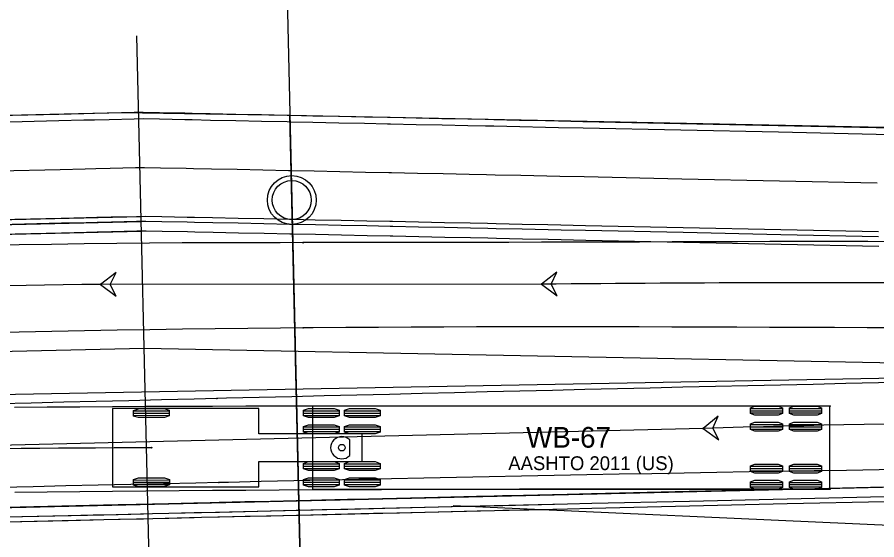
# Model space of a CAD drawing. Extents: x -70 to 701944, y -4 to 666871.
# Drawn here: x 664765.9 to 664853.9, y 656687.8 to 656741.4 of the extents above; entities that cross this region are included whole.
import ezdxf

# ---------------------------------------------------------------- set-up
doc = ezdxf.new("R2010")
doc.units = 0
for name, color, linetype in [('R_Detour', 7, 'Continuous'), ('R_Draft', 7, 'Continuous'), ('R_Drive', 7, 'Continuous'), ('R_No Plot', 7, 'Continuous'), ('R_Proposed Road', 7, 'Continuous'), ('R_Striping', 7, 'Continuous'), ('R_Water', 7, 'Continuous'), ('T_Indications', 7, 'Continuous'), ('T_Vehicle Path Lt Minor', 7, 'Continuous'), ('T_Vehicle Path Rt', 7, 'Continuous')]:
    doc.layers.add(name, color=color, linetype=linetype)

msp = doc.modelspace()

# ---------------------------------------------------------------- linework, layer by layer
at = {"layer": 'R_Detour'}
msp.add_line((664792.031, 656807.534), (664794.944, 656682.847), dxfattribs=at)
at = {"layer": 'R_Draft'}
msp.add_line((664779.481, 656682.485), (664778.149, 656739.517), dxfattribs=at)
at = {"layer": 'R_Drive'}
msp.add_lwpolyline([(664863.88, 656729.191), (664853.873, 656729.402), (664843.865, 656729.613), (664833.857, 656729.824), (664823.85, 656730.035), (664821.348, 656730.087), (664820.018, 656730.115), (664817.367, 656730.171), (664814.716, 656730.227), (664813.842, 656730.245), (664812.063, 656730.283), (664809.412, 656730.339), (664806.761, 656730.395), (664804.112, 656730.45), (664803.834, 656730.456), (664801.465, 656730.506), (664798.821, 656730.562), (664796.181, 656730.617), (664793.827, 656730.667), (664793.546, 656730.673), (664790.916, 656730.728), (664788.292, 656730.784), (664785.675, 656730.839), (664783.819, 656730.878), (664783.066, 656730.894), (664780.464, 656730.948), (664778.815, 656730.983), (664777.873, 656730.961), (664775.292, 656730.901), (664773.817, 656730.866), (664772.722, 656730.841), (664770.163, 656730.781), (664763.819, 656730.633)], dxfattribs=at)
at = {"layer": 'R_No Plot'}
msp.add_line((667813.841, 656555.62), (664810.544, 656691.315), dxfattribs=at)
for points in [[(664793.811, 656731.333), (664776.567, 656731.598), (664678.361, 656729.304), (664666.519, 656729.359), (664635.945, 656732.6), (664627.222, 656684.211), (664649.677, 656681.165), (664794.944, 656682.847)], [(664946.11, 656728.25), (664793.811, 656731.333), (664794.944, 656682.847), (664896.068, 656685.209), (664944.911, 656685.1)]]:
    msp.add_lwpolyline(points, close=True, dxfattribs=at)
msp.add_circle((664794.013, 656722.669), 2.5, dxfattribs=at)
at = {"layer": 'R_Proposed Road'}
msp.add_line((664679.299, 656689.148), (664895.858, 656694.206), dxfattribs=at)
for points in [[(664863.865, 656729.858), (664853.857, 656730.069), (664843.849, 656730.279), (664833.842, 656730.49), (664823.834, 656730.701), (664821.332, 656730.754), (664820.002, 656730.782), (664817.352, 656730.838), (664814.7, 656730.893), (664813.826, 656730.912), (664812.048, 656730.949), (664809.396, 656731.005), (664806.745, 656731.061), (664804.096, 656731.117), (664803.819, 656731.123), (664801.449, 656731.173), (664798.805, 656731.228), (664796.166, 656731.284), (664793.811, 656731.333), (664793.53, 656731.339), (664790.901, 656731.395), (664788.277, 656731.45), (664785.66, 656731.505), (664783.803, 656731.544), (664783.05, 656731.56), (664780.449, 656731.615), (664778.8, 656731.65), (664777.857, 656731.628), (664775.277, 656731.567), (664773.801, 656731.533), (664772.707, 656731.507), (664770.148, 656731.448), (664763.804, 656731.299)], [(664863.88, 656729.191), (664853.873, 656729.402), (664843.865, 656729.613), (664833.857, 656729.824), (664823.85, 656730.035), (664821.348, 656730.087), (664820.018, 656730.115), (664817.367, 656730.171), (664814.716, 656730.227), (664813.842, 656730.245), (664812.063, 656730.283), (664809.412, 656730.339), (664806.761, 656730.395), (664804.112, 656730.45), (664803.834, 656730.456), (664801.465, 656730.506), (664798.821, 656730.562), (664796.181, 656730.617), (664793.827, 656730.667), (664793.546, 656730.673), (664790.916, 656730.728), (664788.292, 656730.784), (664785.675, 656730.839), (664783.819, 656730.878), (664783.066, 656730.894), (664780.464, 656730.948), (664778.815, 656730.983), (664777.873, 656730.961), (664775.292, 656730.901), (664773.817, 656730.866), (664772.722, 656730.841), (664770.163, 656730.781), (664763.819, 656730.633)], [(664853.989, 656724.403), (664843.982, 656724.614), (664833.974, 656724.825), (664823.966, 656725.036), (664821.464, 656725.089), (664820.134, 656725.117), (664817.484, 656725.172), (664814.832, 656725.228), (664813.959, 656725.247), (664812.18, 656725.284), (664809.528, 656725.34), (664806.877, 656725.396), (664804.228, 656725.452), (664803.951, 656725.458), (664801.581, 656725.507), (664798.938, 656725.563), (664796.298, 656725.619), (664793.943, 656725.668), (664793.663, 656725.674), (664791.033, 656725.73), (664788.409, 656725.785), (664785.792, 656725.84), (664783.936, 656725.879), (664783.182, 656725.895), (664780.581, 656725.95), (664778.932, 656725.985), (664777.989, 656725.963), (664775.409, 656725.902), (664773.933, 656725.868), (664772.839, 656725.842), (664770.28, 656725.782), (664763.936, 656725.634)], [(664854.106, 656719.405), (664844.098, 656719.616), (664834.091, 656719.826), (664824.083, 656720.037), (664821.581, 656720.09), (664820.251, 656720.118), (664817.601, 656720.174), (664814.949, 656720.23), (664814.076, 656720.248), (664812.297, 656720.286), (664809.645, 656720.341), (664806.994, 656720.397), (664804.345, 656720.453), (664804.068, 656720.459), (664801.698, 656720.509), (664799.055, 656720.564), (664796.415, 656720.62), (664794.06, 656720.67), (664793.78, 656720.676), (664791.15, 656720.731), (664788.526, 656720.786), (664785.909, 656720.841), (664784.053, 656720.881), (664783.299, 656720.896), (664780.698, 656720.951), (664779.049, 656720.986), (664778.106, 656720.964), (664775.526, 656720.904), (664774.05, 656720.869), (664772.956, 656720.844), (664770.397, 656720.784), (664764.053, 656720.636)], [(664854.118, 656718.905), (664844.11, 656719.116), (664834.102, 656719.327), (664824.095, 656719.537), (664821.593, 656719.59), (664820.263, 656719.618), (664817.612, 656719.674), (664814.961, 656719.73), (664814.087, 656719.748), (664812.309, 656719.786), (664809.657, 656719.842), (664807.006, 656719.897), (664804.357, 656719.953), (664804.08, 656719.959), (664801.71, 656720.009), (664799.066, 656720.065), (664796.426, 656720.12), (664794.072, 656720.17), (664793.791, 656720.176), (664791.161, 656720.231), (664788.537, 656720.286), (664785.92, 656720.342), (664784.064, 656720.381), (664783.311, 656720.397), (664780.709, 656720.451), (664779.06, 656720.486), (664778.118, 656720.464), (664775.538, 656720.404), (664774.062, 656720.369), (664772.968, 656720.344), (664770.409, 656720.284), (664764.064, 656720.136)], [(664854.141, 656717.905), (664844.133, 656718.116), (664834.126, 656718.327), (664824.118, 656718.538), (664821.616, 656718.59), (664820.286, 656718.618), (664817.636, 656718.674), (664814.984, 656718.73), (664814.111, 656718.748), (664812.332, 656718.786), (664809.68, 656718.842), (664807.029, 656718.898), (664804.38, 656718.953), (664804.103, 656718.959), (664801.733, 656719.009), (664799.09, 656719.065), (664796.45, 656719.121), (664794.095, 656719.17), (664793.815, 656719.176), (664791.185, 656719.231), (664788.561, 656719.287), (664785.944, 656719.342), (664784.088, 656719.381), (664783.334, 656719.397), (664780.733, 656719.452), (664779.084, 656719.486), (664778.141, 656719.464), (664775.561, 656719.404), (664774.085, 656719.37), (664772.991, 656719.344), (664770.432, 656719.284), (664764.088, 656719.136)], [(664924.976, 656694.446), (664922.27, 656694.461), (664915.666, 656694.465), (664914.882, 656694.463), (664909.063, 656694.424), (664904.788, 656694.373), (664902.46, 656694.338), (664895.858, 656694.206), (664894.706, 656694.179), (664884.709, 656693.946), (664874.712, 656693.712), (664864.714, 656693.479), (664854.717, 656693.245), (664844.72, 656693.012), (664834.723, 656692.778), (664824.725, 656692.545), (664822.226, 656692.486), (664814.728, 656692.311), (664804.731, 656692.078), (664794.733, 656691.844), (664784.736, 656691.611), (664779.738, 656691.494), (664774.739, 656691.377), (664764.742, 656691.144)], [(664854.717, 656693.245), (664844.72, 656693.012), (664834.723, 656692.778), (664824.725, 656692.545), (664822.226, 656692.486), (664820.897, 656692.455), (664818.25, 656692.394), (664815.601, 656692.332), (664814.728, 656692.311), (664812.951, 656692.27), (664810.302, 656692.208), (664807.654, 656692.146), (664805.008, 656692.084), (664804.731, 656692.078), (664802.364, 656692.022), (664799.723, 656691.961), (664797.086, 656691.899), (664794.733, 656691.844), (664794.453, 656691.838), (664791.826, 656691.776), (664789.205, 656691.715), (664786.59, 656691.654), (664784.736, 656691.611), (664783.984, 656691.593), (664781.385, 656691.532), (664779.738, 656691.494), (664778.795, 656691.472), (664776.215, 656691.412), (664774.739, 656691.377), (664773.645, 656691.352), (664771.086, 656691.292), (664764.742, 656691.144)], [(664924.969, 656693.446), (664922.266, 656693.461), (664915.669, 656693.465), (664914.885, 656693.463), (664909.073, 656693.424), (664904.802, 656693.374), (664902.477, 656693.338), (664895.881, 656693.206), (664894.73, 656693.18), (664884.732, 656692.946), (664874.735, 656692.713), (664864.738, 656692.479), (664854.74, 656692.246), (664844.743, 656692.012), (664834.746, 656691.779), (664824.749, 656691.545), (664822.249, 656691.487), (664814.751, 656691.312), (664804.754, 656691.078), (664794.757, 656690.844), (664784.76, 656690.611), (664779.761, 656690.494), (664774.762, 656690.377), (664764.765, 656690.144)], [(664924.965, 656692.946), (664922.264, 656692.961), (664915.67, 656692.965), (664914.887, 656692.963), (664909.078, 656692.924), (664904.809, 656692.874), (664902.485, 656692.838), (664895.893, 656692.707), (664894.741, 656692.68), (664884.744, 656692.446), (664874.747, 656692.213), (664864.749, 656691.979), (664854.752, 656691.746), (664844.755, 656691.512), (664834.758, 656691.279), (664824.76, 656691.045), (664822.261, 656690.987), (664814.763, 656690.812), (664804.766, 656690.578), (664794.769, 656690.345), (664784.771, 656690.111), (664779.773, 656689.994), (664774.774, 656689.878), (664764.777, 656689.644)], [(664854.74, 656692.246), (664844.743, 656692.012), (664834.746, 656691.779), (664824.749, 656691.545), (664822.249, 656691.487), (664820.921, 656691.456), (664818.273, 656691.394), (664815.624, 656691.332), (664814.751, 656691.312), (664812.975, 656691.27), (664810.326, 656691.208), (664807.677, 656691.146), (664805.031, 656691.084), (664804.754, 656691.078), (664802.387, 656691.023), (664799.746, 656690.961), (664797.109, 656690.899), (664794.757, 656690.844), (664794.477, 656690.838), (664791.849, 656690.777), (664789.228, 656690.715), (664786.614, 656690.654), (664784.76, 656690.611), (664784.007, 656690.593), (664781.408, 656690.533), (664779.761, 656690.494), (664778.818, 656690.472), (664776.238, 656690.412), (664774.762, 656690.377), (664773.668, 656690.352), (664771.109, 656690.292), (664764.765, 656690.144)], [(664854.752, 656691.746), (664844.755, 656691.512), (664834.758, 656691.279), (664824.76, 656691.045), (664822.261, 656690.987), (664820.932, 656690.956), (664818.285, 656690.894), (664815.636, 656690.832), (664814.763, 656690.812), (664812.986, 656690.77), (664810.337, 656690.708), (664807.689, 656690.646), (664805.043, 656690.585), (664804.766, 656690.578), (664802.399, 656690.523), (664799.758, 656690.461), (664797.121, 656690.4), (664794.769, 656690.345), (664794.488, 656690.338), (664791.861, 656690.277), (664789.24, 656690.215), (664786.625, 656690.154), (664784.771, 656690.111), (664784.019, 656690.094), (664781.42, 656690.033), (664779.773, 656689.994), (664778.83, 656689.972), (664776.25, 656689.912), (664774.774, 656689.878), (664773.68, 656689.852), (664771.121, 656689.792), (664764.777, 656689.644)]]:
    msp.add_lwpolyline(points, dxfattribs=at)
at = {"layer": 'R_Striping'}
for p, q in [((664678.925, 656705.144), (664778.898, 656707.479)), ((664778.898, 656707.479), (664895.601, 656705.203)), ((664679.018, 656701.145), (664895.601, 656705.203))]:
    msp.add_line(p, q, dxfattribs=at)
at = {"layer": 'R_Water'}
msp.add_circle((664794.013, 656722.669), 2, dxfattribs=at)
at = {"layer": 'T_Indications'}
for p, q in [((664678.61, 656718.64), (664778.582, 656720.975)), ((664678.621, 656718.14), (664778.594, 656720.475)), ((664678.645, 656717.14), (664778.617, 656719.475))]:
    msp.add_line(p, q, dxfattribs=at)
at = {"layer": 'T_Vehicle Path Lt Minor'}
for p, q in [((664790.639, 656701.284), (664775.639, 656701.284)), ((664775.639, 656701.284), (664775.639, 656693.284)), ((664777.802, 656701.045), (664781.468, 656701.064)), ((664790.639, 656698.717), (664790.639, 656701.284)), ((664795.205, 656701.055), (664798.872, 656701.055)), ((664849.139, 656701.534), (664796.139, 656701.534)), ((664796.139, 656701.534), (664796.139, 656693.034)), ((664799.405, 656701.055), (664803.072, 656701.055)), ((664840.989, 656701.305), (664844.289, 656701.305)), ((664840.989, 656701.076), (664844.289, 656701.076)), ((664844.989, 656701.305), (664848.289, 656701.305)), ((664844.989, 656701.076), (664848.289, 656701.076)), ((664849.139, 656693.034), (664849.139, 656701.534)), ((664777.803, 656700.816), (664781.47, 656700.835)), ((664777.804, 656700.587), (664781.471, 656700.606)), ((664795.205, 656700.826), (664798.872, 656700.826)), ((664795.205, 656700.597), (664798.872, 656700.597)), ((664799.405, 656700.826), (664803.072, 656700.826)), ((664799.405, 656700.597), (664803.072, 656700.597)), ((664840.989, 656700.847), (664844.289, 656700.847)), ((664844.989, 656700.847), (664848.289, 656700.847)), ((664795.205, 656699.405), (664798.872, 656699.405)), ((664795.205, 656699.176), (664798.872, 656699.176)), ((664799.405, 656699.405), (664803.072, 656699.405)), ((664799.405, 656699.176), (664803.072, 656699.176)), ((664840.989, 656699.655), (664844.289, 656699.655)), ((664840.989, 656699.426), (664844.289, 656699.426)), ((664840.989, 656699.197), (664844.289, 656699.197)), ((664844.989, 656699.655), (664848.289, 656699.655)), ((664844.989, 656699.426), (664848.289, 656699.426)), ((664844.989, 656699.197), (664848.289, 656699.197)), ((664801.239, 656698.717), (664790.639, 656698.717)), ((664795.205, 656698.947), (664798.872, 656698.947)), ((664799.405, 656698.947), (664803.072, 656698.947)), ((664801.239, 656695.851), (664801.239, 656698.717)), ((664799.947, 656696.476), (664799.947, 656698.092)), ((664790.639, 656693.284), (664790.639, 656695.851)), ((664790.639, 656695.851), (664801.239, 656695.851)), ((664795.205, 656695.622), (664798.872, 656695.622)), ((664799.405, 656695.622), (664803.072, 656695.622)), ((664795.205, 656695.392), (664798.872, 656695.392)), ((664795.205, 656695.163), (664798.872, 656695.163)), ((664799.405, 656695.392), (664803.072, 656695.392)), ((664799.405, 656695.163), (664803.072, 656695.163)), ((664840.989, 656695.372), (664844.289, 656695.372)), ((664840.989, 656695.142), (664844.289, 656695.142)), ((664840.989, 656694.913), (664844.289, 656694.913)), ((664844.989, 656695.372), (664848.289, 656695.372)), ((664844.989, 656695.142), (664848.289, 656695.142)), ((664844.989, 656694.913), (664848.289, 656694.913)), ((664777.807, 656693.962), (664781.473, 656693.981)), ((664795.205, 656693.972), (664798.872, 656693.972)), ((664799.405, 656693.972), (664803.072, 656693.972)), ((664775.639, 656693.284), (664790.639, 656693.284)), ((664775.639, 656693.284), (664775.639, 656693.284)), ((664777.808, 656693.733), (664781.474, 656693.752)), ((664777.809, 656693.504), (664781.476, 656693.523)), ((664795.205, 656693.742), (664798.872, 656693.742)), ((664795.205, 656693.513), (664798.872, 656693.513)), ((664796.139, 656693.034), (664849.139, 656693.034)), ((664796.139, 656693.034), (664796.139, 656693.034)), ((664799.405, 656693.742), (664803.072, 656693.742)), ((664799.405, 656693.513), (664803.072, 656693.513)), ((664840.989, 656693.722), (664844.289, 656693.722)), ((664840.989, 656693.492), (664844.289, 656693.492)), ((664840.989, 656693.263), (664844.289, 656693.263)), ((664844.989, 656693.722), (664848.289, 656693.722)), ((664844.989, 656693.492), (664848.289, 656693.492)), ((664844.989, 656693.263), (664848.289, 656693.263))]:
    msp.add_line(p, q, dxfattribs=at)
for points in [[(664849.139, 656701.534), (664845.605, 656701.534), (664842.072, 656701.534), (664838.539, 656701.534), (664835.005, 656701.534), (664831.472, 656701.534), (664827.939, 656701.534), (664824.405, 656701.534), (664820.872, 656701.534), (664817.339, 656701.534), (664813.805, 656701.534), (664810.272, 656701.534), (664806.739, 656701.534), (664803.205, 656701.534), (664799.672, 656701.534), (664796.139, 656701.534), (664796.139, 656701.534), (664792.722, 656701.532), (664789.305, 656701.527), (664785.889, 656701.519), (664782.472, 656701.507), (664779.055, 656701.491), (664775.639, 656701.473), (664775.639, 656701.473), (664772.295, 656701.452), (664768.952, 656701.428), (664765.609, 656701.401)], [(664849.139, 656693.034), (664845.605, 656693.034), (664842.072, 656693.034), (664838.539, 656693.034), (664835.005, 656693.033), (664831.472, 656693.032), (664827.939, 656693.03), (664824.405, 656693.026), (664820.872, 656693.022), (664817.339, 656693.016), (664813.805, 656693.009), (664810.272, 656693), (664806.739, 656692.989), (664803.205, 656692.977), (664799.672, 656692.962), (664796.139, 656692.946), (664792.722, 656692.927), (664789.306, 656692.907), (664785.889, 656692.884), (664782.473, 656692.86), (664779.056, 656692.832), (664775.64, 656692.803), (664775.64, 656692.803), (664772.304, 656692.772), (664768.968, 656692.738), (664765.633, 656692.702)]]:
    msp.add_lwpolyline(points, dxfattribs=at)
for points in [[(664777.805, 656700.53), (664777.802, 656701.102), (664778.314, 656701.277), (664780.954, 656701.291), (664781.468, 656701.121), (664781.471, 656700.549), (664780.959, 656700.374), (664778.319, 656700.361)], [(664795.205, 656700.54), (664795.205, 656701.112), (664795.719, 656701.284), (664798.359, 656701.284), (664798.872, 656701.112), (664798.872, 656700.54), (664798.359, 656700.367), (664795.719, 656700.367)], [(664799.405, 656700.54), (664799.405, 656701.112), (664799.919, 656701.284), (664802.559, 656701.284), (664803.072, 656701.112), (664803.072, 656700.54), (664802.559, 656700.367), (664799.919, 656700.367)], [(664840.989, 656700.79), (664840.989, 656701.362), (664841.451, 656701.534), (664843.827, 656701.534), (664844.289, 656701.362), (664844.289, 656700.79), (664843.827, 656700.617), (664841.451, 656700.617)], [(664844.989, 656700.79), (664844.989, 656701.362), (664845.451, 656701.534), (664847.827, 656701.534), (664848.289, 656701.362), (664848.289, 656700.79), (664847.827, 656700.617), (664845.451, 656700.617)], [(664795.205, 656698.89), (664795.205, 656699.462), (664795.719, 656699.634), (664798.359, 656699.634), (664798.872, 656699.462), (664798.872, 656698.89), (664798.359, 656698.717), (664795.719, 656698.717)], [(664799.405, 656698.89), (664799.405, 656699.462), (664799.919, 656699.634), (664802.559, 656699.634), (664803.072, 656699.462), (664803.072, 656698.89), (664802.559, 656698.717), (664799.919, 656698.717)], [(664840.989, 656699.14), (664840.989, 656699.712), (664841.451, 656699.884), (664843.827, 656699.884), (664844.289, 656699.712), (664844.289, 656699.14), (664843.827, 656698.967), (664841.451, 656698.967)], [(664844.989, 656699.14), (664844.989, 656699.712), (664845.451, 656699.884), (664847.827, 656699.884), (664848.289, 656699.712), (664848.289, 656699.14), (664847.827, 656698.967), (664845.451, 656698.967)], [(664795.205, 656695.106), (664795.205, 656695.678), (664795.719, 656695.851), (664798.359, 656695.851), (664798.872, 656695.678), (664798.872, 656695.106), (664798.359, 656694.934), (664795.719, 656694.934)], [(664799.405, 656695.106), (664799.405, 656695.678), (664799.919, 656695.851), (664802.559, 656695.851), (664803.072, 656695.678), (664803.072, 656695.106), (664802.559, 656694.934), (664799.919, 656694.934)], [(664840.989, 656694.856), (664840.989, 656695.428), (664841.451, 656695.601), (664843.827, 656695.601), (664844.289, 656695.428), (664844.289, 656694.856), (664843.827, 656694.684), (664841.451, 656694.684)], [(664844.989, 656694.856), (664844.989, 656695.428), (664845.451, 656695.601), (664847.827, 656695.601), (664848.289, 656695.428), (664848.289, 656694.856), (664847.827, 656694.684), (664845.451, 656694.684)], [(664777.809, 656693.447), (664777.806, 656694.019), (664778.319, 656694.194), (664780.959, 656694.208), (664781.473, 656694.038), (664781.476, 656693.466), (664780.963, 656693.291), (664778.324, 656693.277)], [(664795.205, 656693.456), (664795.205, 656694.028), (664795.719, 656694.201), (664798.359, 656694.201), (664798.872, 656694.028), (664798.872, 656693.456), (664798.359, 656693.284), (664795.719, 656693.284)], [(664799.405, 656693.456), (664799.405, 656694.028), (664799.919, 656694.201), (664802.559, 656694.201), (664803.072, 656694.028), (664803.072, 656693.456), (664802.559, 656693.284), (664799.919, 656693.284)], [(664840.989, 656693.206), (664840.989, 656693.778), (664841.451, 656693.951), (664843.827, 656693.951), (664844.289, 656693.778), (664844.289, 656693.206), (664843.827, 656693.034), (664841.451, 656693.034)], [(664844.989, 656693.206), (664844.989, 656693.778), (664845.451, 656693.951), (664847.827, 656693.951), (664848.289, 656693.778), (664848.289, 656693.206), (664847.827, 656693.034), (664845.451, 656693.034)]]:
    msp.add_lwpolyline(points, close=True, dxfattribs=at)
for centre, radius in [((664849.139, 656701.534), 0.0417), ((664799.139, 656697.284), 0.34), ((664779.639, 656697.284), 0.0417), ((664849.139, 656693.034), 0.0417)]:
    msp.add_circle(centre, radius, dxfattribs=at)
for centre, radius, start, end in [((664799.139, 656697.284), 1.143, 45, 315), ((664799.139, 652964.088), 3733.247, 90.299276, 92.17005)]:
    msp.add_arc(centre, radius, start, end, dxfattribs=at)
at = {"layer": 'T_Vehicle Path Rt'}
for p, q in [((664819.591, 656714.04), (664774.423, 656714.024)), ((664836.137, 656699.258), (664718.041, 656696.403))]:
    msp.add_line(p, q, dxfattribs=at)
for points in [[(664795.177, 656718.3), (664792.836, 656718.297), (664789.49, 656718.293), (664786.145, 656718.283), (664782.799, 656718.266), (664779.454, 656718.242), (664776.108, 656718.211), (664772.762, 656718.173), (664769.417, 656718.128), (664766.073, 656718.077), (664762.73, 656718.018), (664759.386, 656717.953), (664756.043, 656717.881), (664752.7, 656717.802), (664749.356, 656717.716), (664746.014, 656717.623), (664742.671, 656717.524), (664739.328, 656717.418), (664736.32, 656717.317)], [(664856.37, 656718.401), (664853.026, 656718.408), (664849.683, 656718.411), (664846.339, 656718.411), (664842.996, 656718.406), (664839.652, 656718.398), (664836.308, 656718.386), (664832.965, 656718.373), (664829.622, 656718.362), (664826.278, 656718.352), (664822.935, 656718.343), (664819.592, 656718.335), (664816.248, 656718.329), (664812.905, 656718.323), (664809.56, 656718.317), (664806.216, 656718.312), (664802.871, 656718.308), (664799.526, 656718.304), (664796.181, 656718.301), (664795.177, 656718.3)], [(664795.187, 656709.563), (664792.844, 656709.541), (664789.498, 656709.507), (664786.152, 656709.467), (664782.806, 656709.423), (664779.461, 656709.373), (664776.116, 656709.318), (664772.771, 656709.259), (664769.431, 656709.193), (664766.105, 656709.123), (664762.778, 656709.047), (664759.452, 656708.966), (664756.126, 656708.878), (664752.8, 656708.786), (664749.475, 656708.687), (664746.15, 656708.582), (664742.825, 656708.472), (664739.5, 656708.356), (664736.508, 656708.246)], [(664856.271, 656709.556), (664852.937, 656709.573), (664849.604, 656709.589), (664846.271, 656709.603), (664842.937, 656709.616), (664839.604, 656709.628), (664836.27, 656709.639), (664832.937, 656709.649), (664829.604, 656709.657), (664826.27, 656709.662), (664822.936, 656709.665), (664819.603, 656709.666), (664816.269, 656709.663), (664812.924, 656709.658), (664809.577, 656709.648), (664806.23, 656709.635), (664802.883, 656709.618), (664799.537, 656709.597), (664796.19, 656709.571), (664795.187, 656709.563)], [(664860.775, 656704.042), (664857.436, 656703.982), (664854.096, 656703.917), (664850.757, 656703.847), (664847.417, 656703.775), (664844.078, 656703.702), (664840.739, 656703.626), (664837.4, 656703.55), (664834.061, 656703.472), (664830.722, 656703.394), (664827.383, 656703.315), (664824.044, 656703.235), (664820.706, 656703.155), (664817.368, 656703.075), (664814.031, 656702.994), (664810.693, 656702.913), (664807.356, 656702.832), (664804.019, 656702.751), (664800.682, 656702.67), (664797.346, 656702.589), (664794.009, 656702.507), (664790.672, 656702.426), (664787.336, 656702.344), (664786.335, 656702.32)], [(664786.335, 656702.32), (664784, 656702.263), (664780.663, 656702.182), (664777.327, 656702.1), (664773.991, 656702.019), (664770.654, 656701.938), (664767.318, 656701.856), (664763.982, 656701.775), (664760.646, 656701.694), (664757.309, 656701.612), (664753.973, 656701.531), (664750.637, 656701.45), (664747.301, 656701.369), (664743.965, 656701.294), (664740.628, 656701.229)], [(664860.829, 656695.097), (664857.503, 656695.051), (664854.176, 656695.003), (664850.85, 656694.953), (664847.524, 656694.901), (664844.197, 656694.847), (664840.871, 656694.791), (664837.545, 656694.734), (664834.218, 656694.675), (664830.889, 656694.614), (664827.556, 656694.552), (664824.222, 656694.489), (664820.888, 656694.424), (664817.554, 656694.359), (664814.219, 656694.292), (664810.884, 656694.224), (664807.549, 656694.156), (664804.214, 656694.086), (664800.879, 656694.016), (664797.544, 656693.945), (664794.208, 656693.874), (664790.872, 656693.801), (664787.537, 656693.729), (664786.536, 656693.707)], [(664786.536, 656693.707), (664784.201, 656693.655), (664780.865, 656693.581), (664777.529, 656693.507), (664774.193, 656693.433), (664770.857, 656693.358), (664767.522, 656693.284), (664764.186, 656693.21), (664760.85, 656693.136), (664757.514, 656693.062), (664754.177, 656692.988), (664750.841, 656692.913), (664747.505, 656692.839), (664744.169, 656692.765), (664740.833, 656692.691)]]:
    msp.add_lwpolyline(points, dxfattribs=at)
for points in [[(664774.423, 656714.024), (664776.01, 656712.807), (664775.423, 656714.024), (664776.009, 656715.242)], [(664819.591, 656714.04), (664821.19, 656712.838), (664820.591, 656714.05), (664821.166, 656715.273)], [(664836.137, 656699.258), (664837.758, 656698.086), (664837.137, 656699.286), (664837.689, 656700.52)]]:
    msp.add_lwpolyline(points, close=True, dxfattribs=at)
for centre in [(664795.177, 656718.3), (664795.177, 656718.3), (664819.591, 656714.04), (664819.591, 656714.04), (664774.423, 656714.024), (664774.423, 656714.024), (664795.187, 656709.563), (664795.187, 656709.563), (664786.335, 656702.32), (664786.335, 656702.32), (664836.137, 656699.258), (664836.137, 656699.258), (664786.536, 656693.707), (664786.536, 656693.707)]:
    msp.add_circle(centre, 0.0417, dxfattribs=at)
for centre, radius, start, end in [((664848.718, 653818.261), 2895.926, 88.654053, 90.576292), ((664795.016, 655040.991), 1673.159, 90.705217, 94.886375), ((664899.131, 654487.747), 2212.408, 88.212624, 91.631599)]:
    msp.add_arc(centre, radius, start, end, dxfattribs=at)

# ---------------------------------------------------------------- texts
at = {"layer": 'T_Vehicle Path Lt Minor'}
for s, height, p in [('WB-67', 2.125, (664818.021, 656697.284)), ('AASHTO 2011 (US)', 1.41667, (664816.188, 656694.982))]:
    msp.add_text(s, height=height, rotation=360, dxfattribs=at).set_placement(p)

doc.saveas('drawing.dxf')
